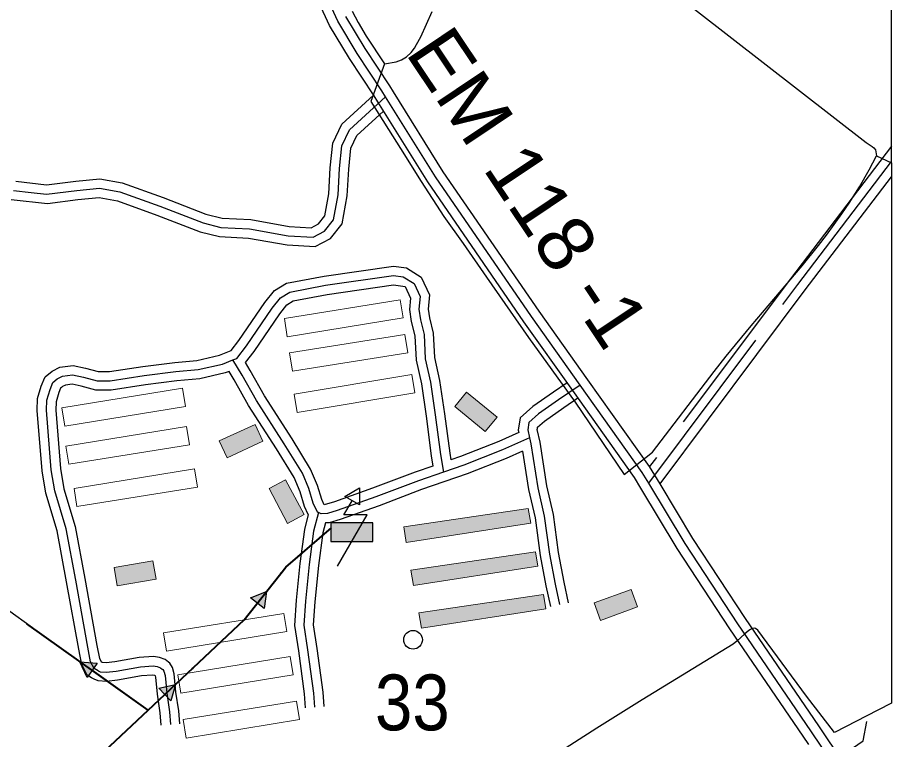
# Model space of a CAD drawing. Extents: x -64005 to -55000, y -89025 to -80000.
# Drawn here: x -55940 to -55001, y -83440 to -82664 of the extents above; entities that cross this region are included whole.
import ezdxf
from ezdxf.enums import TextEntityAlignment as Align

# ---------------------------------------------------------------- set-up
doc = ezdxf.new("R2010")
doc.units = 0
doc.header["$LTSCALE"] = 32
doc.linetypes.add('DOT_DASHED', pattern=[7.7, 5, -1.2, 0.3, -1.2])
doc.linetypes.add('LONG_DASHED', pattern=[7.5, 6, -1.5])
for name, color, linetype, lineweight in [('18', 7, 'Continuous', 25), ('20', 7, 'Continuous', 25), ('24', 7, 'Continuous', 25), ('39', 7, 'LONG_DASHED', 25), ('52', 7, 'Continuous', 25), ('6', 7, 'Continuous', 25), ('7', 7, 'Continuous', 13), ('8', 7, 'Continuous', 25)]:
    doc.layers.add(name, color=color, linetype=linetype, lineweight=lineweight)
doc.layers.add('30', color=7, linetype='Continuous')
doc.layers.add('38', color=7, linetype='Continuous')

msp = doc.modelspace()

# ---------------------------------------------------------------- hatches: boundary and pattern name
at = {"layer": '18'}
for points in [[(-55603.06, -83227.49), (-55558.06, -83227.49), (-55558.06, -83207.49), (-55603.06, -83207.49)], [(-55689.36, -83288), (-55672.15, -83281.21), (-55674.88, -83299.51)], [(-55865.17, -83373.43), (-55872.85, -83356.6), (-55854.44, -83358.36)], [(-55787.97, -83385.21), (-55769.97, -83380.97), (-55775.29, -83398.68)]]:
    msp.add_hatch(color=256, dxfattribs=at).paths.add_polyline_path(points)
at = {"layer": '7'}
for points in [[(-55470.05, -83082.44), (-55437.24, -83109.46), (-55424.53, -83094.02), (-55457.34, -83067)], [(-55684.48, -83101.66), (-55723.1, -83119.39), (-55714.76, -83137.56), (-55676.14, -83119.83)], [(-55669.57, -83170.5), (-55649.63, -83208.03), (-55631.97, -83198.64), (-55651.91, -83161.11)], [(-55522.22, -83228.57), (-55388.36, -83207.63), (-55391.02, -83192.12), (-55524.88, -83211.83)], [(-55514.42, -83274.89), (-55380.56, -83253.95), (-55383.22, -83238.45), (-55517.08, -83258.15)], [(-55794.31, -83248.21), (-55836.18, -83255.49), (-55832.75, -83275.19), (-55790.88, -83267.91)], [(-55280.35, -83278.91), (-55320.29, -83293.43), (-55313.45, -83312.23), (-55273.51, -83297.71)], [(-55505.85, -83320.73), (-55372, -83299.79), (-55374.66, -83284.29), (-55508.52, -83304)]]:
    msp.add_hatch(color=256, dxfattribs=at).paths.add_polyline_path(points)

# ---------------------------------------------------------------- linework, layer by layer
at = {"layer": '18'}
for p, q in [((-55638.82, -83244.2), (-55603.06, -83213.19)), ((-55913.58, -83327.59), (-55973.83, -83284.67)), ((-55799.55, -83408.82), (-55859.8, -83365.9))]:
    msp.add_line(p, q, dxfattribs=at)
at = {"layer": '18', "linetype": 'DOT_DASHED', "lineweight": 40}
for points in [[(-55799.55, -83408.82), (-56213.85, -83113.68), (-56334.46, -83035.34)], [(-57366.28, -84880.22), (-57280.56, -84799.12), (-57201.32, -84725.34), (-57111.72, -84639.44), (-57001.22, -84535.99), (-56803.81, -84352.58), (-56800.13, -84349.16), (-56655.47, -84214.11), (-56626.76, -84187.31), (-56550.11, -84115.75), (-56364.73, -83938.99), (-56258.14, -83840.02), (-56026.24, -83620.22), (-55896.2, -83499.07), (-55799.55, -83408.82), (-55696.34, -83311.64), (-55651.45, -83255.16), (-55602.56, -83212.76)]]:
    msp.add_lwpolyline(points, dxfattribs=at)
at = {"layer": '18'}
for points in [[(-55588.3, -83179), (-55572.28, -83169.74), (-55572.28, -83188.24)], [(-55603.06, -83227.49), (-55558.06, -83227.49), (-55558.06, -83207.49), (-55603.06, -83207.49)], [(-55689.36, -83288), (-55672.15, -83281.21), (-55674.88, -83299.51)], [(-55865.17, -83373.43), (-55872.85, -83356.6), (-55854.44, -83358.36)], [(-55787.97, -83385.21), (-55769.97, -83380.97), (-55775.29, -83398.68)]]:
    msp.add_lwpolyline(points, close=True, dxfattribs=at)
for points in [[(-55595.86, -83253.99), (-55564.17, -83198.99), (-55589.17, -83198.99), (-55580.29, -83183.62)], [(-55733.57, -83346.69), (-55696.34, -83311.64), (-55682.12, -83293.75)], [(-55835.63, -83442.51), (-55799.55, -83408.82), (-55781.63, -83391.95)]]:
    msp.add_lwpolyline(points, dxfattribs=at)
for centre in [(-55656.6, -83261.64), (-55893.21, -83342.1), (-55751.77, -83363.83)]:
    msp.add_circle(centre, 0.5, dxfattribs=at)
at = {"layer": '20'}
msp.add_lwpolyline([(-55110.29, -83482.93), (-55095, -83485.77), (-55031, -83441.81), (-55027.13, -83420.95)], dxfattribs=at)
at = {"layer": '24'}
for points in [[(-55319.7, -82571.68), (-55027.83, -82798.59), (-55021.2, -82802.93), (-55019.52, -82804.32), (-55017.77, -82806.8), (-55016.8, -82813.16), (-55000.65, -82820.74), (-55000.74, -81871.81)], [(-55580.16, -82657.8), (-55573.83, -82669.9), (-55565.11, -82684.54), (-55545.61, -82714.07)], [(-55580.16, -82657.8), (-55573.83, -82669.9), (-55565.11, -82684.54), (-55545.61, -82714.07)], [(-55545.61, -82714.07), (-55532.98, -82712.19), (-55527.15, -82710.03), (-55522.01, -82706.74), (-55516.99, -82701.95), (-55513.41, -82697.39), (-55510.93, -82693.61), (-55506.42, -82685.35), (-55494.31, -82658.09)], [(-55545.61, -82714.07), (-55560.01, -82754.78), (-55528.21, -82805.07), (-55506.03, -82840.56), (-55481.63, -82878.28), (-55460.93, -82907.12), (-55435.79, -82943.35), (-55390.68, -83008.43), (-55340.4, -83077.94), (-55287.91, -83155.59), (-55257.4, -83131.37), (-55191.31, -83044.95), (-55178.32, -83028.37), (-55151.37, -82995.81), (-55096.54, -82931.26), (-55078.89, -82909.35), (-55070.33, -82898.23), (-55053.86, -82875.57), (-55046.03, -82864), (-55034.86, -82846.27), (-55024.48, -82828.05), (-55016.8, -82813.16), (-55000.64, -82820.74), (-55000.58, -83401.34)], [(-55061.85, -83432.66), (-55092.1, -83393.71), (-55144.43, -83322.66), (-55146.66, -83320.91), (-55148.34, -83320.65), (-55149.53, -83320.82), (-55152.06, -83321.86), (-55154.07, -83323.16), (-55158.26, -83326.66), (-55166.81, -83334.69), (-55170.84, -83337.75), (-55268.69, -83397.68), (-55317.15, -83427.99), (-55365.16, -83458.96)], [(-55000.58, -83401.34), (-55015.13, -83408.57), (-55061.85, -83432.66)]]:
    msp.add_lwpolyline(points, dxfattribs=at)
at = {"layer": '39'}
msp.add_line((-55944.29, -82850.26), (-55925.08, -82852.44), dxfattribs=at)
at = {"layer": '39', "linetype": 'Continuous'}
for points in [[(-55544.3, -82749.64), (-55548.24, -82743.32), (-55574.78, -82703.15), (-55595.74, -82668.21), (-55641.81, -82568.14), (-55703.2, -82411.52), (-55727.3, -82349.32), (-55768.45, -82233.55), (-55785.56, -82175.56), (-55848.39, -82037.4), (-55854.91, -82020.51)], [(-55335.05, -83059.46), (-55387.39, -82985.82), (-55490.69, -82835.71), (-55544.3, -82749.64)], [(-55261.42, -83164.84), (-55268.41, -83153.24), (-55335.05, -83059.46)], [(-55087.13, -83431.08), (-55165.87, -83315.84), (-55222.44, -83229.55), (-55261.42, -83164.84)], [(-55064.21, -83464.62), (-55075.36, -83448.31), (-55087.13, -83431.08)]]:
    msp.add_lwpolyline(points, dxfattribs=at)
at = {"layer": '39'}
for points in [[(-55925.08, -82852.44), (-55908.64, -82854.3), (-55876.16, -82850.24), (-55851.8, -82847.8), (-55829.88, -82851.85), (-55786.84, -82867.29), (-55740.55, -82885.16), (-55721.28, -82889.97), (-55690.42, -82891.58), (-55649.01, -82898.89), (-55622.21, -82900.52), (-55610.04, -82894.01), (-55600.3, -82881.82), (-55595.43, -82855.02), (-55593.8, -82826.58), (-55591.37, -82802.21), (-55583.24, -82785.14), (-55544.3, -82749.64)], [(-55261.42, -83164.84), (-55101.27, -82951.18), (-55000.65, -82819.08)], [(-55708.33, -83032.33), (-55704.16, -83030.71), (-55693.8, -83017.32), (-55666.17, -82976.73), (-55657.1, -82965.51), (-55647.17, -82959.46), (-55608.75, -82952.12), (-55535.78, -82941.75), (-55525.42, -82943.05), (-55513.76, -82950.39), (-55507.29, -82964.19), (-55508.58, -82978.01), (-55506.86, -82989.23), (-55502.97, -83005.21), (-55501.68, -83031.11), (-55496.06, -83056.15), (-55490.88, -83091.55), (-55485.27, -83133.86), (-55482.19, -83153.09)], [(-55853.23, -83366.56), (-55857.43, -83364.04), (-55861.32, -83356.7), (-55864.34, -83341.15), (-55877.29, -83269.05), (-55887.65, -83213.79), (-55899.75, -83173.21), (-55903.63, -83150.33), (-55908.81, -83086.43), (-55908.38, -83075.64), (-55904.93, -83063.98), (-55901.9, -83056.63), (-55897.15, -83052.75), (-55891.53, -83049.73), (-55880.74, -83048.43), (-55869.08, -83051.02), (-55854.4, -83054.91), (-55840.16, -83054.91), (-55803.89, -83049.28), (-55769.79, -83044.97), (-55745.61, -83042.81), (-55719.71, -83036.76), (-55708.33, -83032.33)], [(-55616.52, -83196.43), (-55617.39, -83196.04), (-55622.14, -83186.12), (-55626.89, -83170.58), (-55633.79, -83154.17), (-55653.22, -83122.66), (-55683.01, -83076.03), (-55698.55, -83048.83), (-55708.33, -83032.33)], [(-55335.05, -83059.46), (-55358.34, -83075.13), (-55379.93, -83090.24), (-55390.29, -83099.74), (-55391.58, -83107.51), (-55389.62, -83116.08)], [(-55389.62, -83116.08), (-55418.79, -83129.1), (-55460.23, -83145.51), (-55482.19, -83153.09)], [(-55389.62, -83116.08), (-55388.13, -83122.62), (-55380.79, -83169.68), (-55373.88, -83200.34), (-55368.27, -83240.92), (-55362.23, -83273.3), (-55357.48, -83295.31)], [(-55482.19, -83153.09), (-55509.03, -83162.35), (-55554.79, -83179.62), (-55596.23, -83194.31), (-55606.59, -83197.33), (-55613.5, -83197.77), (-55616.52, -83196.43)], [(-55616.52, -83196.43), (-55621.7, -83216.34), (-55626.45, -83252.18), (-55630.33, -83291.47), (-55632.07, -83317.37), (-55628.18, -83343.7), (-55621.71, -83390.33), (-55620.84, -83405.44)], [(-55853.23, -83366.56), (-55850.98, -83367.49), (-55844.5, -83368), (-55833.94, -83366.64), (-55807.87, -83362.03), (-55794.23, -83361.01), (-55789.8, -83361.86), (-55786.23, -83363.05), (-55784.35, -83364.55), (-55783.67, -83365.09), (-55782.48, -83366.97), (-55781.29, -83371.4), (-55779.58, -83390.48), (-55776.52, -83410.58), (-55775.49, -83424.04)]]:
    msp.add_lwpolyline(points, dxfattribs=at)
at = {"layer": '52'}
msp.add_circle((-55514.81, -83333.06), 10, dxfattribs=at)
at = {"layer": '6'}
for points in [[(-55089.39, -83445.5), (-55095.39, -83436.72), (-55174.18, -83321.4), (-55230.91, -83234.87), (-55269.99, -83170), (-55276.78, -83158.72), (-55343.2, -83065.25), (-55395.58, -82991.55), (-55499.06, -82841.19), (-55552.79, -82754.93), (-55556.66, -82748.72), (-55583.24, -82708.48), (-55604.6, -82672.89), (-55651.01, -82572.06)], [(-55249.37, -83165.45), (-55260.56, -83147.02), (-55326.9, -83053.67), (-55379.2, -82980.09), (-55482.32, -82830.23), (-55535.81, -82744.35), (-55539.82, -82737.92), (-55566.32, -82697.82), (-55586.88, -82663.53)], [(-55055.96, -83458.96), (-55067.1, -83442.67), (-55078.87, -83425.44), (-55157.56, -83310.28), (-55213.97, -83224.23), (-55249.37, -83165.45)]]:
    msp.add_lwpolyline(points, dxfattribs=at)
at = {"layer": '7'}
for points in [[(-55528.73, -82967.63), (-55653.12, -82987.92), (-55649.94, -83007.52), (-55525.55, -82987.21)], [(-55523.62, -83005.02), (-55647.51, -83024.75), (-55644.33, -83044.36), (-55520.44, -83024.61)], [(-55516.06, -83048.07), (-55642.51, -83069.28), (-55639.33, -83088.88), (-55512.88, -83067.66)], [(-55762.7, -83062.84), (-55892.11, -83083.83), (-55888.93, -83103.43), (-55759.52, -83082.43)], [(-55470.05, -83082.44), (-55437.24, -83109.46), (-55424.53, -83094.02), (-55457.34, -83067)], [(-55758.39, -83103.97), (-55887.8, -83124.96), (-55884.62, -83144.56), (-55755.21, -83123.56)], [(-55684.48, -83101.66), (-55723.1, -83119.39), (-55714.76, -83137.56), (-55676.14, -83119.83)], [(-55749.76, -83149.42), (-55879.17, -83170.41), (-55875.99, -83190.01), (-55746.58, -83169.01)], [(-55669.57, -83170.5), (-55649.63, -83208.03), (-55631.97, -83198.64), (-55651.91, -83161.11)], [(-55522.22, -83228.57), (-55388.36, -83207.63), (-55391.02, -83192.12), (-55524.88, -83211.83)], [(-55514.42, -83274.89), (-55380.56, -83253.95), (-55383.22, -83238.45), (-55517.08, -83258.15)], [(-55794.31, -83248.21), (-55836.18, -83255.49), (-55832.75, -83275.19), (-55790.88, -83267.91)], [(-55280.35, -83278.91), (-55320.29, -83293.43), (-55313.45, -83312.23), (-55273.51, -83297.71)], [(-55505.85, -83320.73), (-55372, -83299.79), (-55374.66, -83284.29), (-55508.52, -83304)], [(-55653.74, -83304.72), (-55783.14, -83325.72), (-55779.96, -83345.32), (-55650.56, -83324.31)], [(-55646.74, -83351.2), (-55767.54, -83370.71), (-55764.36, -83390.31), (-55643.56, -83370.79)], [(-55639.96, -83399.11), (-55762.01, -83418.91), (-55758.81, -83438.67), (-55636.76, -83418.87)]]:
    msp.add_lwpolyline(points, close=True, dxfattribs=at)
at = {"layer": '8'}
for p, q in [((-55946.71, -82860.05), (-55907.76, -82864.26)), ((-55857.7, -83375.54), (-55860.39, -83373.93))]:
    msp.add_line(p, q, dxfattribs=at)
at = {"layer": '8', "linetype": 'LONG_DASHED'}
for points in [[(-55941.88, -82840.47), (-55908.7, -82844.23), (-55877.28, -82840.3), (-55851.38, -82837.71), (-55827.26, -82842.16), (-55783.35, -82857.92), (-55737.53, -82875.61), (-55719.79, -82880.02), (-55689.28, -82881.63), (-55647.83, -82888.94), (-55624.43, -82890.36), (-55616.57, -82886.16), (-55609.69, -82877.55), (-55605.38, -82853.84), (-55603.77, -82825.8), (-55601.15, -82799.48), (-55591.43, -82779.07), (-55557.19, -82747.86)], [(-55000.65, -82802.58), (-55109.25, -82945.15), (-55260.56, -83147.02)], [(-55910.48, -83051.22), (-55910.18, -83050.49), (-55902.73, -83044.4), (-55894.6, -83040.03), (-55880.24, -83038.3), (-55866.71, -83041.3), (-55853.1, -83044.91), (-55840.93, -83044.91), (-55805.28, -83039.38), (-55770.86, -83035.03), (-55747.2, -83032.91), (-55722.67, -83027.18), (-55710.37, -83022.4), (-55701.89, -83011.44), (-55674.2, -82970.76), (-55663.79, -82957.87), (-55650.83, -82949.98), (-55610.39, -82942.25), (-55535.87, -82931.66), (-55521.98, -82933.4), (-55505.96, -82943.48)], [(-55523.4, -82953.39), (-55517.5, -82965.98), (-55518.65, -82978.31), (-55516.68, -82991.17), (-55512.91, -83006.65), (-55511.62, -83032.46), (-55505.9, -83057.97), (-55500.78, -83092.93), (-55495.18, -83135.31), (-55493.4, -83146.38)], [(-55627.36, -83198.38), (-55631.48, -83189.76), (-55636.3, -83173.99), (-55642.71, -83158.76), (-55661.69, -83127.98), (-55691.57, -83081.21), (-55707.2, -83053.86), (-55712.61, -83044.73)], [(-55860.39, -83373.93), (-55864.96, -83371.18), (-55870.85, -83360.07), (-55874.17, -83342.99), (-55887.13, -83270.87), (-55897.38, -83216.15), (-55909.51, -83175.48), (-55913.56, -83151.57), (-55918.83, -83086.64), (-55918.32, -83074), (-55914.37, -83060.64), (-55910.48, -83051.22)], [(-55349.15, -83056.88), (-55364, -83066.88), (-55386.2, -83082.42), (-55399.59, -83094.7), (-55401.77, -83107.82), (-55401.2, -83110.29)], [(-55401.2, -83110.29), (-55422.67, -83119.88), (-55463.7, -83136.13), (-55474.2, -83139.75)], [(-55397.05, -83130.34), (-55390.62, -83171.56), (-55383.73, -83202.13), (-55378.14, -83242.52), (-55372.03, -83275.27), (-55367.25, -83297.42)], [(-55493.4, -83146.38), (-55512.43, -83152.94), (-55558.23, -83170.23), (-55599.3, -83184.79), (-55610.17, -83187.96)], [(-55627.36, -83198.38), (-55631.53, -83214.42), (-55636.39, -83251.03), (-55640.31, -83290.65), (-55642.12, -83317.77), (-55638.08, -83345.12), (-55631.67, -83391.31), (-55630.82, -83406.02)], [(-55777.61, -83357.14), (-55781.39, -83354.12), (-55787.27, -83352.16), (-55793.65, -83350.94), (-55809.11, -83352.1), (-55835.45, -83356.75), (-55844.75, -83357.95), (-55848.63, -83357.64), (-55849.76, -83357.17)], [(-55785.46, -83424.8), (-55786.46, -83411.72), (-55789.51, -83391.68), (-55791.17, -83373.16), (-55791.53, -83371.83)]]:
    msp.add_lwpolyline(points, dxfattribs=at)
at = {"layer": '8'}
for points in [[(-55907.76, -82864.26), (-55875.04, -82860.18), (-55852.22, -82857.89), (-55832.5, -82861.55), (-55790.33, -82876.66), (-55743.57, -82894.71), (-55722.77, -82899.91), (-55691.56, -82901.53), (-55650.19, -82908.84), (-55620, -82910.67), (-55603.51, -82901.86), (-55590.91, -82886.09), (-55585.48, -82856.2), (-55583.83, -82827.36), (-55581.58, -82804.94), (-55575.05, -82791.21), (-55546.44, -82765.12)], [(-55249.37, -83165.45), (-55093.29, -82957.21), (-55000.65, -82835.59)], [(-55505.96, -82943.48), (-55497.08, -82962.41), (-55498.51, -82977.71), (-55497.04, -82987.29), (-55493.03, -83003.77), (-55491.74, -83029.76), (-55486.22, -83054.33), (-55480.98, -83090.17), (-55475.37, -83132.41), (-55474.2, -83139.75)], [(-55695, -83035.2), (-55685.71, -83023.2), (-55658.14, -82982.7), (-55650.41, -82973.15), (-55643.51, -82968.94), (-55607.11, -82961.99), (-55535.7, -82951.84), (-55523.4, -82953.39)], [(-55610.17, -83187.96), (-55612.8, -83182.47), (-55617.48, -83167.17), (-55624.87, -83149.58), (-55644.75, -83117.34), (-55674.45, -83070.85), (-55689.91, -83043.8), (-55695, -83035.2)], [(-55712.61, -83044.73), (-55716.75, -83046.34), (-55744.02, -83052.71), (-55768.72, -83054.91), (-55802.5, -83059.18), (-55839.39, -83064.91), (-55855.7, -83064.91), (-55871.45, -83060.74), (-55881.24, -83058.56), (-55888.46, -83059.43), (-55891.57, -83061.1), (-55892.74, -83062.06), (-55893.62, -83062.78), (-55895.49, -83067.31), (-55898.44, -83077.28), (-55898.79, -83086.22), (-55893.7, -83149.09), (-55889.99, -83170.94), (-55877.92, -83211.43), (-55867.45, -83267.24), (-55854.51, -83339.31), (-55851.79, -83353.33), (-55849.76, -83357.17)], [(-55347.71, -83293.2), (-55352.43, -83271.33), (-55358.4, -83239.32), (-55364.03, -83198.54), (-55370.96, -83167.81), (-55378.3, -83120.73), (-55381.39, -83107.2), (-55381.18, -83105.94), (-55380.99, -83104.78), (-55373.66, -83098.06), (-55352.68, -83083.38), (-55337.56, -83073.19)], [(-55397.05, -83130.34), (-55414.91, -83138.32), (-55456.76, -83154.89), (-55505.63, -83171.76), (-55551.35, -83189.01), (-55593.16, -83203.83), (-55604.85, -83207.24), (-55609.07, -83207.51)], [(-55609.07, -83207.51), (-55611.87, -83218.26), (-55616.51, -83253.33), (-55620.36, -83292.29), (-55622.01, -83316.97), (-55618.27, -83342.28), (-55611.75, -83389.35), (-55610.86, -83404.87)], [(-55765.52, -83423.28), (-55766.58, -83409.44), (-55769.65, -83389.28), (-55771.41, -83369.64), (-55773.22, -83362.91), (-55776.12, -83358.32), (-55777.61, -83357.14)], [(-55791.53, -83371.83), (-55792.33, -83371.56), (-55794.81, -83371.08), (-55806.62, -83371.96), (-55832.43, -83376.53), (-55844.25, -83378.05), (-55853.33, -83377.34), (-55857.7, -83375.54)]]:
    msp.add_lwpolyline(points, dxfattribs=at)

# ---------------------------------------------------------------- texts
at = {"layer": '30', "width": 1.05}
msp.add_text('EM 118 -1', height=60, rotation=303.79, dxfattribs=at).set_placement((-55523.92, -82702.27))
at = {"layer": '38', "width": 0.9}
msp.add_text('33', height=60, rotation=0.006, dxfattribs=at).set_placement((-55515.55, -83430.37), align=Align.CENTER)

doc.saveas('drawing.dxf')
